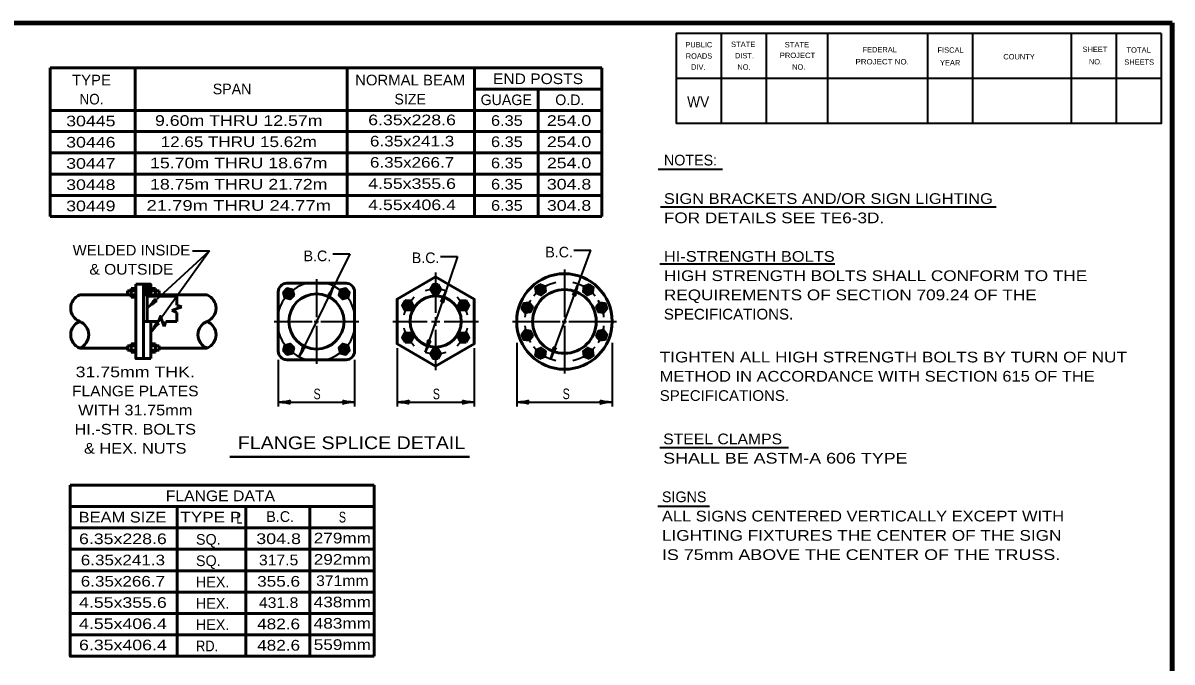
# Model space of a CAD drawing. Extents: x -46 to 809, y -15 to 529.
# Drawn here: x 477.7 to 802.6, y 342 to 522.6 of the extents above; entities that cross this region are included whole.
import ezdxf
from ezdxf.enums import TextEntityAlignment as Align

# ---------------------------------------------------------------- set-up
doc = ezdxf.new("R2010")
doc.units = 0
doc.header["$LTSCALE"] = 1.2
for name, color, linetype, lineweight in [('1', 7, 'Continuous', 35), ('4', 7, 'Continuous', 53), ('61', 7, 'Continuous', 35)]:
    doc.layers.add(name, color=color, linetype=linetype, lineweight=lineweight)

msp = doc.modelspace()

# ---------------------------------------------------------------- hatches: boundary and pattern name
at = {"layer": '1'}
for points in [[(553.747, 446.048, 1), (551.947, 446.048, 1)], [(569.445, 446.048, 1), (567.645, 446.048, 1)], [(594.64, 446.472, 1), (594.176, 448.211, 1)], [(623.522, 446.485, 1), (624.617, 447.913, 1)], [(638.118, 446.485, 1), (637.022, 447.913, 1)], [(587.356, 442.521, 1), (585.626, 443.019, 1)], [(601.46, 442.521, 1), (603.19, 443.019, 1)], [(619.448, 441.726, 1), (621.087, 442.472, 1)], [(642.192, 441.726, 1), (640.553, 442.472, 1)], [(587.356, 433.877, 1), (585.626, 433.379, 1)], [(601.46, 433.877, 1), (603.19, 433.379, 1)], [(619.448, 434.672, 1), (621.087, 433.926, 1)], [(642.192, 434.672, 1), (640.553, 433.926, 1)], [(553.747, 430.35, 1), (551.947, 430.35, 1)], [(569.445, 430.35, 1), (567.645, 430.35, 1)], [(594.64, 429.926, 1), (594.176, 428.187, 1)], [(623.522, 429.913, 1), (624.617, 428.485, 1)], [(638.118, 429.913, 1), (637.022, 428.485, 1)]]:
    msp.add_hatch(color=256, dxfattribs=at).paths.add_polyline_path(points)

# ---------------------------------------------------------------- linework, layer by layer
at = {"layer": '1', "lineweight": 158}
msp.add_line((802.618, -3.544), (802.618, 522.556), dxfattribs=at)
at = {"layer": '1', "lineweight": 13}
msp.add_line((802.618, -3.544), (802.618, 522.556), dxfattribs=at)
at = {"layer": '1', "lineweight": 53}
for p, q in [((485.394, 509.849), (641.394, 509.849)), ((485.394, 509.849), (485.394, 467.849)), ((509.394, 509.849), (509.394, 467.849)), ((569.394, 509.849), (569.394, 467.849)), ((605.394, 509.849), (605.394, 467.849)), ((641.394, 509.849), (641.394, 467.849)), ((605.394, 503.849), (641.394, 503.849)), ((623.394, 503.849), (623.394, 467.849)), ((485.394, 497.849), (641.394, 497.849)), ((485.394, 491.849), (641.394, 491.849)), ((485.394, 485.849), (641.394, 485.849)), ((485.394, 479.849), (641.394, 479.849)), ((485.394, 473.849), (641.394, 473.849)), ((485.394, 467.849), (641.394, 467.849)), ((509.651, 448.699), (511.751, 448.699)), ((511.751, 448.003), (512.448, 448.699)), ((511.751, 447.154), (513.296, 448.699)), ((511.751, 446.306), (513.851, 448.406)), ((552.296, 448.999), (569.096, 448.999)), ((493.751, 445.699), (507.251, 445.699)), ((507.251, 446.899), (509.651, 446.899)), ((507.251, 446.899), (507.251, 445.699)), ((507.251, 445.699), (509.651, 445.699)), ((508.301, 447.499), (508.301, 445.099)), ((508.301, 447.499), (509.651, 447.499)), ((511.751, 445.699), (511.751, 427.699)), ((511.993, 445.699), (513.851, 447.557)), ((512.801, 438.199), (512.801, 445.699)), ((512.801, 445.399), (521.201, 445.399)), ((512.842, 445.699), (513.851, 446.709)), ((513.69, 445.699), (513.851, 445.86)), ((513.851, 447.499), (515.201, 447.499)), ((513.851, 446.899), (516.251, 446.899)), ((513.851, 445.699), (529.751, 445.699)), ((513.851, 445.699), (513.851, 445.399)), ((515.201, 447.499), (515.201, 445.399)), ((515.201, 445.699), (516.251, 445.699)), ((516.251, 446.899), (516.251, 445.699)), ((521.201, 445.399), (521.201, 442.824)), ((549.896, 429.799), (549.896, 446.599)), ((571.496, 429.799), (571.496, 446.599)), ((508.301, 445.099), (509.651, 445.099)), ((522.609, 442.311), (519.793, 441.287)), ((521.201, 442.824), (522.609, 442.311)), ((521.201, 440.774), (519.793, 441.287)), ((521.201, 440.774), (521.201, 438.199)), ((511.751, 438.199), (515.051, 438.199)), ((515.051, 438.199), (516.076, 438.199)), ((518.126, 438.199), (517.614, 436.791)), ((518.126, 438.199), (521.201, 438.199)), ((493.751, 430.699), (507.251, 430.699)), ((507.251, 431.299), (507.251, 430.099)), ((507.251, 431.299), (509.651, 431.299)), ((507.251, 430.099), (509.651, 430.099)), ((508.301, 431.899), (508.301, 429.499)), ((508.301, 431.899), (509.651, 431.899)), ((508.301, 429.499), (509.651, 429.499)), ((513.851, 431.899), (515.201, 431.899)), ((513.851, 431.299), (516.251, 431.299)), ((513.851, 430.099), (516.251, 430.099)), ((513.851, 429.499), (515.201, 429.499)), ((515.201, 431.899), (515.201, 429.499)), ((516.251, 431.299), (516.251, 430.099)), ((516.251, 430.699), (529.751, 430.699)), ((552.296, 427.399), (569.096, 427.399)), ((491.092, 391.95), (576.988, 391.95)), ((576.988, 391.95), (576.988, 343.566)), ((491.092, 385.901), (576.988, 385.901)), ((521.332, 385.901), (521.332, 343.566)), ((540.7, 385.901), (540.7, 343.566)), ((558.844, 385.901), (558.844, 343.566)), ((491.092, 379.853), (576.988, 379.853)), ((491.092, 373.805), (576.988, 373.805)), ((491.092, 367.757), (576.988, 367.757)), ((491.092, 361.709), (576.988, 361.709)), ((491.092, 355.661), (576.988, 355.661)), ((491.092, 349.614), (576.988, 349.614))]:
    msp.add_line(p, q, dxfattribs=at)
at = {"layer": '1'}
for p, q in [((657.354, 481.237), (675.498, 481.237)), ((658.026, 470.581), (752.874, 470.581)), ((512.801, 441.949), (530.471, 458.204)), ((530.471, 458.204), (513.851, 435.049)), ((525.671, 458.204), (530.471, 458.204)), ((626.926, 427.646), (638.245, 458.322)), ((633.445, 458.322), (638.245, 458.322)), ((570.099, 457.277), (555.803, 428.27)), ((565.298, 457.277), (570.099, 457.277)), ((600.592, 456.526), (591.485, 429.537)), ((595.792, 456.526), (600.592, 456.526)), ((594.408, 451.999), (594.408, 440.599)), ((630.82, 452.899), (630.82, 439.399)), ((657.81, 454.453), (707.25, 454.453)), ((560.696, 450.199), (560.696, 439.399)), ((560.696, 438.799), (560.696, 437.599)), ((594.408, 439.399), (594.408, 436.999)), ((630.82, 438.799), (630.82, 437.599)), ((548.696, 438.199), (559.496, 438.199)), ((560.096, 438.199), (561.296, 438.199)), ((560.696, 436.999), (560.696, 426.199)), ((561.896, 438.199), (572.696, 438.199)), ((582.296, 438.199), (592.008, 438.199)), ((593.208, 438.199), (595.608, 438.199)), ((594.408, 435.799), (594.408, 424.399)), ((596.808, 438.199), (606.52, 438.199)), ((616.12, 438.199), (629.62, 438.199)), ((630.22, 438.199), (631.42, 438.199)), ((630.82, 436.999), (630.82, 423.499)), ((632.02, 438.199), (645.52, 438.199)), ((617.32, 432.199), (617.32, 414.199)), ((644.32, 432.199), (644.32, 414.199)), ((583.496, 430.699), (583.496, 414.199)), ((605.32, 430.699), (605.32, 414.199)), ((549.896, 427.399), (549.896, 414.199)), ((571.496, 427.399), (571.496, 414.199)), ((549.896, 415.399), (571.496, 415.399)), ((583.496, 415.399), (605.32, 415.399)), ((617.32, 415.399), (644.32, 415.399)), ((657.831, 402.629), (694.143, 402.629)), ((657.26, 386.026), (671.827, 386.026))]:
    msp.add_line(p, q, dxfattribs=at)
at = {"layer": '1', "lineweight": 40}
msp.add_line((536.253, 399.979), (603.93, 399.979), dxfattribs=at)
at = {"layer": '1', "lineweight": 158}
msp.add_lwpolyline([(802.618, 522.556), (10.918, 522.456), (11.018, -3.544)], dxfattribs=at)
at = {"layer": '1', "lineweight": 53}
for points in [[(509.651, 448.699), (509.651, 427.699), (513.851, 427.699)], [(516.076, 438.199), (516.589, 439.607), (517.614, 436.791)], [(513.851, 438.199), (513.851, 431.899), (513.851, 427.699)], [(491.092, 391.95), (491.092, 343.566), (576.988, 343.566)]]:
    msp.add_lwpolyline(points, dxfattribs=at)
for points in [[(511.751, 445.699), (511.751, 448.699), (513.851, 448.699), (513.851, 445.699)], [(594.408, 450.799), (583.496, 444.499), (583.496, 431.899), (594.408, 425.599), (605.32, 431.899), (605.32, 444.499)]]:
    msp.add_lwpolyline(points, close=True, dxfattribs=at)
for centre, radius in [((630.82, 438.199), 13.5), ((552.847, 446.048), 0.9), ((560.696, 438.199), 7.8), ((568.545, 446.048), 0.9), ((594.408, 438.199), 7.245), ((594.408, 447.341), 0.9), ((630.82, 438.199), 9), ((624.07, 447.199), 0.9), ((637.57, 447.199), 0.9), ((586.491, 442.77), 0.9), ((602.325, 442.77), 0.9), ((620.268, 442.099), 0.9), ((641.372, 442.099), 0.9), ((586.491, 433.628), 0.9), ((602.325, 433.628), 0.9), ((620.268, 434.299), 0.9), ((641.372, 434.299), 0.9), ((552.847, 430.35), 0.9), ((568.545, 430.35), 0.9), ((594.408, 429.057), 0.9), ((624.07, 429.199), 0.9), ((637.57, 429.199), 0.9)]:
    msp.add_circle(centre, radius, dxfattribs=at)
for centre, radius, start, end in [((552.296, 446.599), 2.4, 90, 180), ((569.096, 446.599), 2.4, 0, 90), ((495.235, 441.949), 4.033, 111.59181, 248.40819), ((528.267, 441.949), 4.033, 291.59181, 68.40819), ((495.235, 434.449), 4.033, 111.59181, 248.40819), ((492.267, 434.449), 4.033, 291.59181, 68.40819), ((531.235, 434.449), 4.033, 111.59181, 248.40819), ((528.267, 434.449), 4.033, 291.59181, 68.40819), ((552.296, 429.799), 2.4, 180, 270), ((569.096, 429.799), 2.4, 270, 0)]:
    msp.add_arc(centre, radius, start, end, dxfattribs=at)
at = {"layer": '1'}
for centre, radius, start, end in [((560.696, 438.199), 11.1, 103.35118, 166.64882), ((560.696, 438.199), 11.1, 13.35118, 76.64882), ((630.82, 438.199), 11.25, 102.31777, 140.46884), ((630.82, 438.199), 11.25, 39.53116, 77.68223), ((594.408, 438.199), 9.142, 71.35498, 108.64502), ((594.408, 438.199), 9.142, 131.35521, 168.64477), ((594.408, 438.199), 9.142, 11.35523, 48.64479), ((630.82, 438.199), 11.25, 148.00596, 173.8768), ((630.82, 438.199), 11.25, 6.1232, 31.99404), ((560.696, 438.199), 11.1, 193.35118, 256.64882), ((560.696, 438.199), 11.1, 283.35118, 346.64882), ((594.408, 438.199), 9.142, 191.35523, 228.64511), ((594.408, 438.199), 9.142, 311.35489, 348.64477), ((630.82, 438.199), 11.25, 186.1232, 211.70086), ((630.82, 438.199), 11.25, 328.06359, 353.8768), ((594.408, 438.199), 9.142, 251.3553, 288.6447), ((630.82, 438.199), 11.25, 219.22018, 257.68223), ((630.82, 438.199), 11.25, 282.31777, 320.54408)]:
    msp.add_arc(centre, radius, start, end, dxfattribs=at)
at = {"layer": '1', "lineweight": 40}
for centre, major_axis, ratio, start_param, end_param in [((634.01, 447.579), (0.927, 1.904), 0.07063, 3.1407148, 5.41811), ((634.01, 447.579), (0.927, 1.904), 0.07063, 3.1407148, 5.41811), ((634.572, 447.409), (0.566, 2.075), 0.122415, 0.8963533, 3.1415927), ((634.572, 447.409), (0.566, 2.075), 0.122415, 0.8963533, 3.1415927), ((564.767, 447.034), (1.121, 1.797), 0.07063, 3.1407148, 5.41811), ((564.767, 447.034), (1.121, 1.797), 0.07063, 3.1407148, 5.41811), ((565.308, 446.807), (0.779, 2.005), 0.122415, 0.8963533, 3.1415927), ((565.308, 446.807), (0.779, 2.005), 0.122415, 0.8963533, 3.1415927), ((596.66, 445.668), (-0.874, -1.93), 0.07063, 6.2823074, 8.5597026), ((596.66, 445.668), (-0.874, -1.93), 0.07063, 6.2823074, 8.5597026), ((597.226, 445.515), (0.508, 2.09), 0.122415, 0.8963533, 3.1415927), ((597.226, 445.515), (0.508, 2.09), 0.122415, 0.8963533, 3.1415927), ((513.54, 443.08), (-1.45, -1.589), 0.122415, 0.8963533, 3.1415927), ((513.54, 443.08), (-1.45, -1.589), 0.122415, 0.8963533, 3.1415927), ((513.963, 442.672), (1.694, 1.272), 0.07063, 6.2823074, 8.5597026), ((513.963, 442.672), (1.694, 1.272), 0.07063, 6.2823074, 8.5597026), ((514.345, 436.306), (-1.097, -1.85), 0.122415, 0.8963533, 3.1415927), ((514.842, 435.993), (1.4, 1.589), 0.07063, 6.2823074, 8.5597026), ((591.59, 430.883), (-0.508, -2.09), 0.122415, 0.8963533, 3.1415927), ((592.156, 430.73), (0.874, 1.93), 0.07063, 6.2823074, 8.5597026), ((556.084, 429.591), (-0.779, -2.005), 0.122415, 0.8963533, 3.1415927), ((556.625, 429.364), (-1.121, -1.797), 0.07063, 3.1407148, 5.41811), ((627.068, 428.989), (-0.566, -2.075), 0.122415, 0.8963533, 3.1415927), ((627.629, 428.819), (-0.927, -1.904), 0.07063, 3.1407148, 5.41811), ((551.206, 415.731), (-2.143, -0.187), 0.122415, 0.8963533, 3.1415927), ((551.206, 415.731), (-2.143, -0.187), 0.122415, 0.8963533, 3.1415927), ((584.806, 415.731), (-2.143, -0.187), 0.122415, 0.8963533, 3.1415927), ((584.806, 415.731), (-2.143, -0.187), 0.122415, 0.8963533, 3.1415927), ((618.629, 415.731), (-2.143, -0.187), 0.122415, 0.8963533, 3.1415927), ((551.241, 415.145), (-2.108, 0.211), 0.07063, 3.1407148, 5.41811), ((551.241, 415.145), (-2.108, 0.211), 0.07063, 3.1407148, 5.41811), ((570.187, 415.067), (2.143, 0.187), 0.122415, 0.8963533, 3.1415927), ((570.187, 415.067), (2.143, 0.187), 0.122415, 0.8963533, 3.1415927), ((570.151, 415.653), (2.108, -0.211), 0.07063, 3.1407148, 5.41811), ((570.151, 415.653), (2.108, -0.211), 0.07063, 3.1407148, 5.41811), ((584.841, 415.145), (-2.108, 0.211), 0.07063, 3.1407148, 5.41811), ((584.841, 415.145), (-2.108, 0.211), 0.07063, 3.1407148, 5.41811), ((604.01, 415.067), (2.143, 0.187), 0.122415, 0.8963533, 3.1415927), ((604.01, 415.067), (2.143, 0.187), 0.122415, 0.8963533, 3.1415927), ((603.975, 415.653), (2.108, -0.211), 0.07063, 3.1407148, 5.41811), ((603.975, 415.653), (2.108, -0.211), 0.07063, 3.1407148, 5.41811), ((618.665, 415.145), (-2.108, 0.211), 0.07063, 3.1407148, 5.41811), ((643.01, 415.067), (2.143, 0.187), 0.122415, 0.8963533, 3.1415927), ((642.975, 415.653), (2.108, -0.211), 0.07063, 3.1407148, 5.41811)]:
    msp.add_ellipse(centre, major_axis=major_axis, ratio=ratio, start_param=start_param, end_param=end_param, dxfattribs=at)
at = {"layer": '4'}
for points in [[(595.159, 448.64), (593.659, 448.641), (592.908, 447.342), (593.657, 446.042), (595.157, 446.042), (595.908, 447.34)], [(623.873, 448.686), (625.259, 448.113), (625.456, 446.625), (624.266, 445.712), (622.88, 446.285), (622.684, 447.772)], [(637.766, 448.686), (636.38, 448.113), (636.184, 446.625), (637.374, 445.712), (638.76, 446.285), (638.956, 447.772)], [(553.908, 447.109), (554.296, 445.66), (553.235, 444.599), (551.787, 444.987), (551.398, 446.436), (552.459, 447.497)], [(567.484, 447.109), (567.096, 445.66), (568.157, 444.599), (569.606, 444.987), (569.994, 446.436), (568.933, 447.497)], [(585.765, 444.083), (584.991, 442.798), (585.717, 441.485), (587.217, 441.458), (587.99, 442.742), (587.265, 444.055)], [(603.051, 444.083), (603.825, 442.798), (603.099, 441.485), (601.599, 441.458), (600.826, 442.742), (601.551, 444.055)], [(620.794, 443.504), (621.747, 442.346), (621.221, 440.941), (619.741, 440.694), (618.788, 441.853), (619.314, 443.257)], [(640.846, 443.504), (639.893, 442.346), (640.419, 440.941), (641.899, 440.694), (642.852, 441.853), (642.326, 443.257)], [(620.794, 432.894), (621.747, 434.053), (621.221, 435.457), (619.741, 435.704), (618.788, 434.545), (619.314, 433.141)], [(640.846, 432.894), (639.893, 434.053), (640.419, 435.457), (641.899, 435.704), (642.852, 434.545), (642.326, 433.141)], [(585.765, 432.315), (584.991, 433.6), (585.717, 434.913), (587.217, 434.941), (587.99, 433.656), (587.265, 432.343)], [(603.051, 432.315), (603.825, 433.6), (603.099, 434.913), (601.599, 434.941), (600.826, 433.656), (601.551, 432.343)], [(553.908, 429.289), (554.296, 430.738), (553.235, 431.799), (551.787, 431.411), (551.398, 429.962), (552.459, 428.901)], [(567.484, 429.289), (567.096, 430.738), (568.157, 431.799), (569.606, 431.411), (569.994, 429.962), (568.933, 428.901)], [(595.159, 427.758), (593.659, 427.757), (592.908, 429.056), (593.657, 430.356), (595.157, 430.356), (595.908, 429.058)], [(623.873, 427.712), (625.259, 428.285), (625.456, 429.773), (624.266, 430.686), (622.88, 430.113), (622.684, 428.626)], [(637.766, 427.712), (636.38, 428.285), (636.184, 429.773), (637.374, 430.686), (638.76, 430.113), (638.956, 428.626)]]:
    msp.add_lwpolyline(points, close=True, dxfattribs=at)
at = {"layer": '61'}
for p, q in [((675.118, 519.556), (675.118, 494.156)), ((687.818, 519.556), (687.818, 494.156)), ((705.218, 519.556), (705.218, 494.156)), ((733.518, 519.556), (733.518, 494.156)), ((746.218, 519.556), (746.218, 494.156)), ((774.118, 519.556), (774.118, 494.156)), ((786.818, 519.556), (786.818, 494.156)), ((799.518, 506.856), (662.418, 506.856))]:
    msp.add_line(p, q, dxfattribs=at)
for points in [[(799.518, 519.556), (662.418, 519.556), (662.418, 494.156)], [(799.518, 519.556), (799.518, 494.156), (662.418, 494.156)]]:
    msp.add_lwpolyline(points, dxfattribs=at)

# ---------------------------------------------------------------- texts
at = {"layer": '1'}
for s, height, width, p in [('TYPE', 3, 1.05, (497.085, 504.931)), ('NORMAL BEAM', 3, 1.05, (587.202, 504.931)), ('END POSTS', 3, 1.1, (623.356, 505.29)), ('NO.', 3, 0.95, (497.085, 499.531)), ('30445', 3, 1.25, (496.906, 493.359)), ('9.60m THRU 12.57m', 3, 1.25, (538.732, 493.49)), ('6.35x228.6', 3, 1.25, (587.738, 493.667)), ('6.35', 3, 1.15, (614.549, 493.49)), ('254.0', 3, 1.25, (632.127, 493.49)), ('6.35x241.3', 3, 1.2, (587.738, 487.667)), ('30446', 3, 1.25, (496.906, 487.359)), ('12.65 THRU 15.62m', 3, 1.2, (538.732, 487.49)), ('6.35', 3, 1.15, (614.549, 487.49)), ('254.0', 3, 1.25, (632.127, 487.49)), ('30447', 3, 1.25, (496.906, 481.359)), ('15.70m THRU 18.67m', 3, 1.25, (538.732, 481.49)), ('6.35x266.7', 3, 1.2, (587.738, 481.667)), ('6.35', 3, 1.15, (614.549, 481.49)), ('254.0', 3, 1.25, (632.127, 481.49)), ('30448', 3, 1.25, (496.906, 475.359)), ('18.75m THRU 21.72m', 3, 1.25, (538.732, 475.49)), ('4.55x355.6', 3, 1.25, (587.738, 475.667)), ('6.35', 3, 1.15, (614.549, 475.49)), ('304.8', 3, 1.25, (632.127, 475.49)), ('30449', 3, 1.25, (496.906, 469.359)), ('21.79m THRU 24.77m', 3, 1.3, (538.732, 469.49)), ('4.55x406.4', 3, 1.25, (587.738, 469.667)), ('6.35', 3, 1.15, (614.549, 469.49)), ('304.8', 3, 1.25, (632.127, 469.49)), ('WELDED INSIDE', 3, 1.05, (508.381, 456.851)), ('& OUTSIDE', 3, 1.1, (508.381, 451.451)), ('31.75mm THK.', 3, 1.25, (509.465, 422.45)), ('FLANGE PLATES', 3, 1.1, (509.465, 417.05)), ('S', 3, 0.75, (560.888, 416.219)), ('S', 3, 0.75, (594.608, 416.219)), ('S', 3, 0.75, (631.312, 416.246)), ('WITH 31.75mm', 3, 1.15, (509.465, 411.65)), ('HI.-STR. BOLTS', 3, 1.15, (509.465, 406.25)), ('& HEX. NUTS', 3, 1.15, (509.465, 400.85)), ('FLANGE SPLICE DETAIL', 3.6, 1.15, (570.605, 402.117)), ('FLANGE DATA', 3.024, 1.1, (533.534, 387.413)), ('BEAM SIZE', 3.024, 1.15, (505.854, 381.389)), ('TYPE P', 3.024, 1.2, (530.84, 381.389)), ('L', 3.024, 0.75, (538.893, 381.054)), ('S', 3.024, 0.75, (568.052, 381.389)), ('6.35x228.6', 3, 1.25, (505.973, 375.278)), ('304.8', 3.024, 1.25, (550, 375.298)), ('279mm', 3.024, 1.2, (568.022, 375.476)), ('6.35x241.3', 3, 1.2, (505.973, 369.278)), ('317.5', 3.024, 1.1, (550, 369.274)), ('292mm', 3.024, 1.2, (568.022, 369.452)), ('6.35x266.7', 3, 1.2, (505.973, 363.278)), ('355.6', 3.024, 1.2, (550, 363.25)), ('371mm', 3.024, 1.1, (568.022, 363.428)), ('4.55x355.6', 3, 1.25, (505.973, 357.278)), ('431.8', 3.024, 1.1, (550, 357.226)), ('438mm', 3.024, 1.2, (568.022, 357.404)), ('4.55x406.4', 3, 1.25, (505.973, 351.278)), ('482.6', 3.024, 1.2, (550, 351.202)), ('483mm', 3.024, 1.2, (568.022, 351.38)), ('6.35x406.4', 3, 1.25, (505.973, 345.278)), ('482.6', 3.024, 1.2, (550, 345.178)), ('559mm', 3.024, 1.2, (568.022, 345.356))]:
    msp.add_text(s, height=height, dxfattribs=dict(at, width=width)).set_placement(p, align=Align.CENTER)
for s, height, p in [('SPAN', 3, (536.837, 502.411)), ('SIZE', 3, (587.202, 499.531)), ('GUAGE', 3, (614.362, 499.352)), ('O.D.', 3, (632.35, 499.352)), ('B.C.', 3, (560.971, 455.241)), ('B.C.', 3, (629.317, 456.315)), ('B.C.', 3, (591.566, 454.704)), ('B.C.', 3.024, (550.448, 381.558))]:
    msp.add_text(s, height=height, dxfattribs=at).set_placement(p, align=Align.CENTER)
for s, height, width, p in [('WV', 3.048, 0.95, (665.518, 498.756)), ('SIGN BRACKETS AND/OR SIGN LIGHTING', 3.024, 1.15, (658.938, 471.421)), ('FOR DETAILS SEE TE6-3D.', 3.024, 1.2, (658.938, 465.973)), ('HI-STRENGTH BOLTS', 3.024, 1.15, (658.938, 455.077)), ('HIGH STRENGTH BOLTS SHALL CONFORM TO THE', 3.024, 1.2, (658.938, 449.629)), ('REQUIREMENTS OF SECTION 709.24 OF THE', 3.024, 1.2, (658.938, 444.205)), ('SPECIFICATIONS.', 3.024, 1.05, (658.938, 438.781)), ('SPECIFICATIONS.', 3.024, 1.05, (658.938, 438.757)), ('TIGHTEN ALL HIGH STRENGTH BOLTS BY TURN OF NUT', 3.024, 1.2, (657.768, 426.626)), ('METHOD IN ACCORDANCE WITH SECTION 615 OF THE', 3.024, 1.15, (657.768, 421.202)), ('SPECIFICATIONS.', 3.024, 1.05, (657.768, 415.754)), ('STEEL CLAMPS', 3.024, 1.1, (658.743, 403.493)), ('SHALL BE ASTM-A 606 TYPE', 3.024, 1.25, (658.743, 398.045)), ('ALL SIGNS CENTERED VERTICALLY EXCEPT WITH', 3.024, 1.15, (658.388, 381.682)), ('LIGHTING FIXTURES THE CENTER OF THE SIGN', 3.024, 1.2, (658.388, 376.234)), ('IS 75mm ABOVE THE CENTER OF THE TRUSS.', 3.024, 1.25, (658.388, 370.786)), ('RD.', 3.024, 0.9, (526.636, 344.982))]:
    msp.add_text(s, height=height, dxfattribs=dict(at, width=width)).set_placement(p)
for s, p in [('NOTES:', (658.938, 482.293)), ('SIGNS', (658.388, 387.13)), ('SQ.', (526.636, 375.102)), ('SQ.', (526.636, 369.078)), ('HEX.', (526.636, 363.054)), ('HEX.', (526.636, 357.03)), ('HEX.', (526.636, 351.006))]:
    msp.add_text(s, height=3.024, dxfattribs=at).set_placement(p)
at = {"layer": '61'}
for s, height, rotation, p in [('PUBLIC', 1.525, 0.033, (665.018, 515.656)), ('ROADS', 1.525, 0.124, (665.118, 512.456)), ('DIST.', 1.525, 0.056, (679.018, 512.556)), ('FEDERAL', 1.523, 0.007, (715.118, 514.256)), ('FISCAL', 1.525, 359.942, (736.318, 514.156)), ('COUNTY', 1.523, 0.069, (754.918, 512.256)), ('SHEET', 1.525, 0.059, (777.318, 514.356)), ('DIV.', 1.525, 359.932, (666.618, 509.356)), ('YEAR', 1.523, 0.105, (737.018, 510.556)), ('SHEETS', 1.523, 359.959, (789.118, 510.756))]:
    msp.add_text(s, height=height, rotation=rotation, dxfattribs=at).set_placement(p)
for s, rotation, width, p in [('STATE', 0.059, 1.05, (677.918, 515.756)), ('STATE', 0.059, 1.05, (693.118, 515.656)), ('PROJECT', 359.908, 1.05, (691.718, 512.656)), ('TOTAL', 359.926, 1.05, (789.718, 514.156)), ('NO.', 359.852, 0.9, (679.718, 509.356)), ('NO.', 0.225, 0.9, (695.218, 509.356)), ('PROJECT NO.', 359.922, 1.1, (713.118, 510.856)), ('NO.', 359.852, 0.9, (779.118, 510.856))]:
    msp.add_text(s, height=1.525, rotation=rotation, dxfattribs=dict(at, width=width)).set_placement(p)

doc.saveas('drawing.dxf')
